Omron CX-Programmer project 新工程 (CX-Programmer 7.30)

# PLC 欧姆龙CP1H: CP1H X

## Global symbols (name address type ; comment)
D0 CHANNEL  ; 设定频率参考值
D1 CHANNEL  ; 设定加速时间1
D10 CHANNEL  ; 当前频率值
D11 CHANNEL  ; 当前频率值-高字
D12 CHANNEL  ; 当前电流值
D2 CHANNEL  ; 设定加速时间1低字
D20 CHANNEL  ; 线圈地址

## Program 新程序1 (cyclic task 0)

### Section 段1

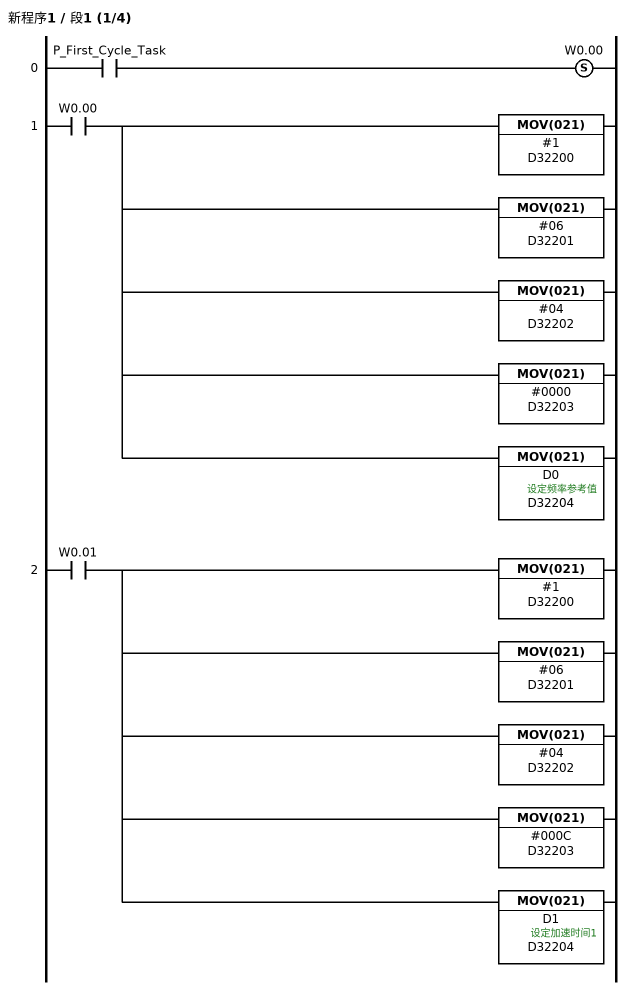
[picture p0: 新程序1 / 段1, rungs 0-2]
; rung 0
LD P_First_Cycle_Task
SET W0.00
; rung 1
LD W0.00
MOV(021) #1 D32200
MOV(021) #06 D32201
MOV(021) #04 D32202
MOV(021) #0000 D32203
MOV(021) D0 D32204  ; 设定频率参考值
; rung 2
LD W0.01
MOV(021) #1 D32200
MOV(021) #06 D32201
MOV(021) #04 D32202
MOV(021) #000C D32203
MOV(021) D1 D32204  ; 设定加速时间1

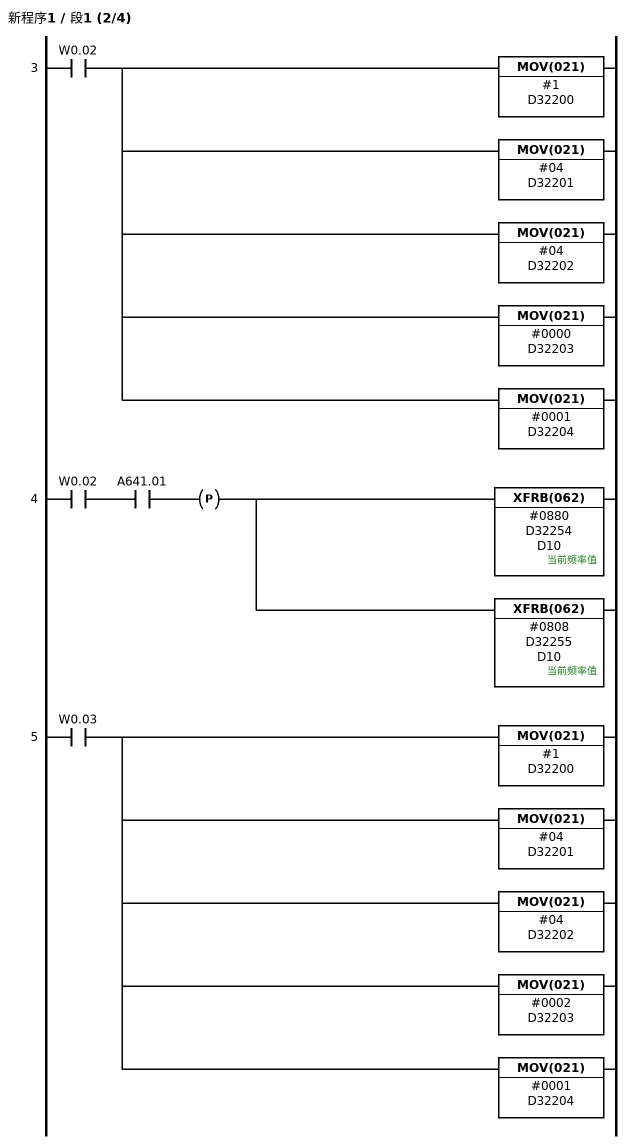
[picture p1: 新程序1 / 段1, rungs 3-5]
; rung 3
LD W0.02
MOV(021) #1 D32200
MOV(021) #04 D32201
MOV(021) #04 D32202
MOV(021) #0000 D32203
MOV(021) #0001 D32204
; rung 4
LD W0.02
AND A641.01
UP(521)
XFRB(062) #0880 D32254 D10  ; 当前频率值
XFRB(062) #0808 D32255 D10  ; 当前频率值
; rung 5
LD W0.03
MOV(021) #1 D32200
MOV(021) #04 D32201
MOV(021) #04 D32202
MOV(021) #0002 D32203
MOV(021) #0001 D32204

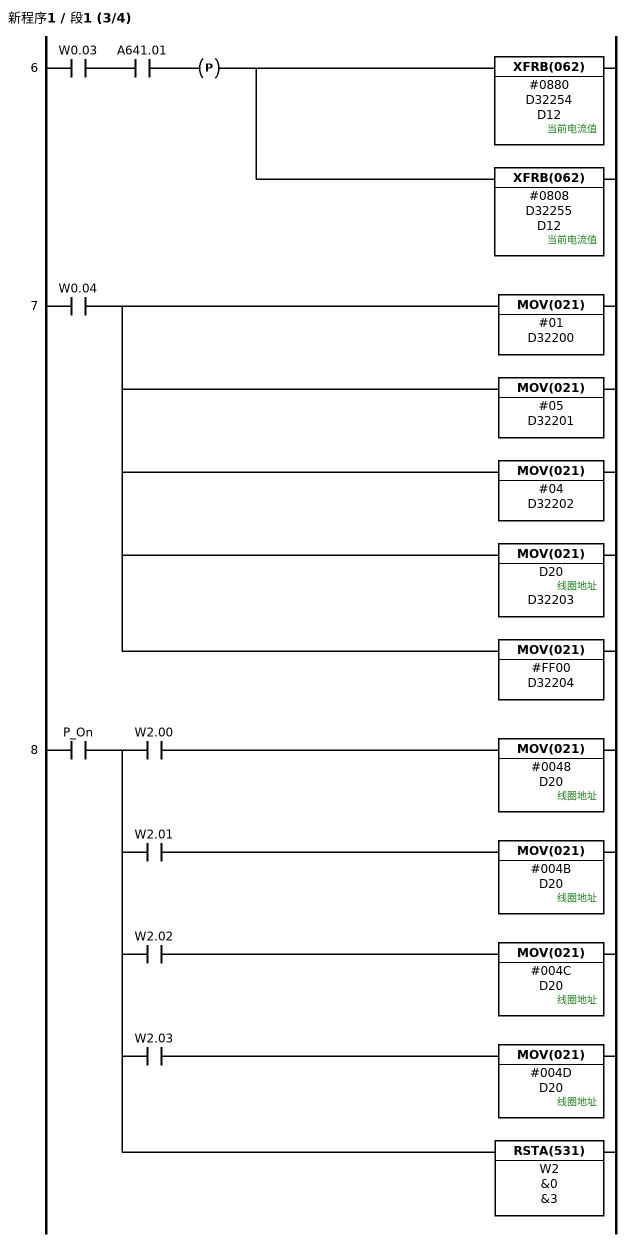
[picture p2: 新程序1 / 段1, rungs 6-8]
; rung 6
LD W0.03
AND A641.01
UP(521)
XFRB(062) #0880 D32254 D12  ; 当前电流值
XFRB(062) #0808 D32255 D12  ; 当前电流值
; rung 7
LD W0.04
MOV(021) #01 D32200
MOV(021) #05 D32201
MOV(021) #04 D32202
MOV(021) D20 D32203  ; 线圈地址
MOV(021) #FF00 D32204
; rung 8
LD P_On
OUT TR0
AND W2.00
MOV(021) #0048 D20  ; 线圈地址
LD TR0
AND W2.01
MOV(021) #004B D20  ; 线圈地址
LD TR0
AND W2.02
MOV(021) #004C D20  ; 线圈地址
LD TR0
AND W2.03
MOV(021) #004D D20  ; 线圈地址
LD TR0
RSTA(531) W2 &0 &3

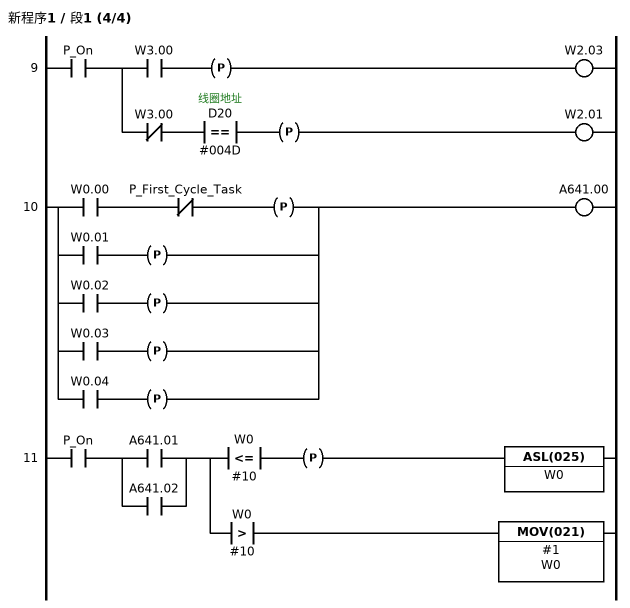
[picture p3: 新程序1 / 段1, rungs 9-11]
; rung 9
LD P_On
OUT TR0
AND W3.00
UP(521)
OUT W2.03
LD TR0
ANDNOT W3.00
AND=(300) D20 #004D  ; 线圈地址
UP(521)
OUT W2.01
; rung 10
LD W0.00
ANDNOT P_First_Cycle_Task
UP(521)
LD W0.01
UP(521)
ORLD
LD W0.02
UP(521)
ORLD
LD W0.03
UP(521)
ORLD
LD W0.04
UP(521)
ORLD
OUT A641.00
; rung 11
LD P_On
LD A641.01
OR A641.02
ANDLD
OUT TR0
AND<=(315) W0 #10
UP(521)
ASL(025) W0
LD TR0
AND>(320) W0 #10
MOV(021) #1 W0
; rung 12
END(001)

### Section END
; rung 0
END(001)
